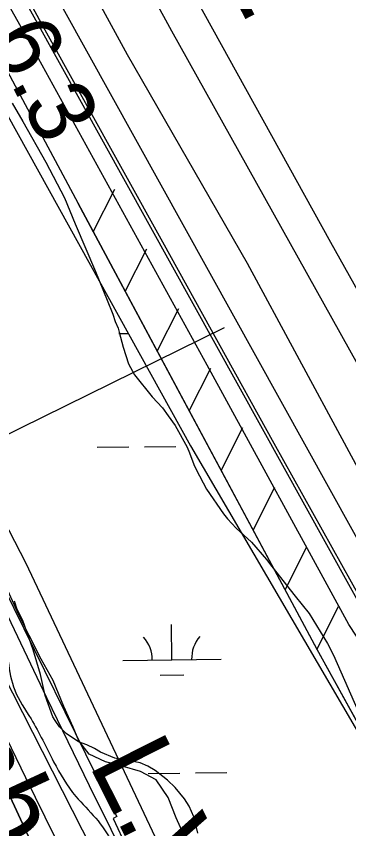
# Model space of a CAD drawing. Extents: x 3684037 to 3722149, y 433263 to 459021.
# Drawn here: x 3712028 to 3712366, y 440224 to 441051 of the extents above; entities that cross this region are included whole.
import ezdxf

# ---------------------------------------------------------------- set-up
doc = ezdxf.new("R2010")
doc.units = 0
for name, color, linetype in [('V-FLOD-BASE', 7, 'Continuous'), ('V-LEVE-TOET', 7, 'Continuous'), ('V-RIVR-EDGE', 7, 'Continuous'), ('V-RIVR-IDEN', 7, 'Continuous'), ('V-RIVR-RANG', 7, 'Continuous'), ('V-RIVR-RANG-IDEN', 7, 'Continuous'), ('V-ROAD-CNTR', 7, 'Continuous'), ('V-RRAP-FSHR', 7, 'Continuous'), ('V-RRAP-RVMT', 7, 'Continuous'), ('V-SITE-VEGE', 7, 'Continuous'), ('V-SURV-LINE', 7, 'Continuous'), ('V-TOPO-DPTH', 7, 'Continuous'), ('V-TOPO-MINR', 7, 'Continuous'), ('V-TOPO-WATR', 7, 'Continuous'), ('V-TOPO-WATR-IDEN', 7, 'Continuous'), ('V-UTIL-IDEN', 7, 'Continuous'), ('V-WETL-SWMP', 7, 'Continuous')]:
    doc.layers.add(name, color=color, linetype=linetype)

msp = doc.modelspace()

# ---------------------------------------------------------------- linework, layer by layer
at = {"layer": 'V-FLOD-BASE'}
msp.add_lwpolyline([(3712398.74, 440422.41), (3712290.71, 440616.44), (3712177.45, 440821.47), (3712056.06, 441040.41), (3711925.95, 441279.62), (3711796.44, 441506.66), (3711752.3, 441587.16), (3711730.23, 441628.29), (3711718.6, 441652.61), (3711654.1, 441794.53), (3711570.43, 441978.74), (3711454.8, 442224.92)], dxfattribs=at)
at = {"layer": 'V-LEVE-TOET'}
for points in [[(3711516.68, 442246.95), (3711627.09, 442006.55), (3711773.51, 441696.66), (3711965.19, 441335.23), (3712141.19, 441012.62), (3712263.15, 440800.06), (3712414.75, 440519.15), (3712489.08, 440395.79), (3712504.77, 440365.67), (3712551.23, 440281.69), (3712698.85, 440026.88)], [(3712594.9, 440025.08), (3712449.12, 440283.98), (3712438.67, 440303.09), (3712428.22, 440316.99), (3712416.03, 440329.72), (3712408.48, 440342.46), (3712402.09, 440356.95), (3712396.85, 440373.75), (3712391.04, 440388.23), (3712382.9, 440407.34), (3712366.65, 440432.25), (3712222.6, 440696.36), (3712039.64, 441028.82), (3711814.87, 441429.61), (3711723.69, 441588.89), (3711716.72, 441602.79), (3711694.64, 441649.13), (3711565.06, 441926.01), (3711441.87, 442202.32)]]:
    msp.add_lwpolyline(points, dxfattribs=at)
at = {"layer": 'V-RIVR-EDGE'}
msp.add_spline([(3710881.85, 442907.17), (3710900.3, 442872.76), (3710912.89, 442844.25), (3710926.84, 442815.27), (3710939.89, 442789.92), (3710950.22, 442762.31), (3710961.88, 442723.85), (3710972.69, 442706.64), (3710987.55, 442681.29), (3711004.19, 442645.52), (3711013.15, 442612.95), (3711017.62, 442590.33), (3711028.39, 442559.55), (3711043.23, 442525.61), (3711061.24, 442493.46), (3711083.32, 442464.01), (3711101.79, 442435.48), (3711123.37, 442385.69), (3711146.29, 442329.57), (3711160.2, 442285.22), (3711177.71, 442238.15), (3711205.6, 442178.4), (3711227.63, 442127.25), (3711258.71, 442079.24), (3711273.08, 442038.51), (3711277.08, 442009.57), (3711279.27, 441982.43), (3711285.11, 441965.69), (3711299.53, 441946.66), (3711314.4, 441925.82), (3711322.93, 441901.39), (3711344.09, 441864.26), (3711361.61, 441818.09), (3711381.38, 441766.05), (3711387.6, 441724.88), (3711408.3, 441685.04), (3711430.33, 441634.35), (3711446.97, 441597.23), (3711483.42, 441524.79), (3711505.9, 441474.1), (3711521.64, 441439.69), (3711545.49, 441393.97), (3711577.41, 441319.28), (3711605.29, 441255.01), (3711666.49, 441137.74), (3711693.94, 441084.32), (3711722.25, 441011.45), (3711736.18, 440977.51), (3711773.54, 440908.24), (3711800.07, 440850.29), (3711813.99, 440812.28), (3711827.94, 440785.11), (3711836.49, 440767.46), (3711872.07, 440711.3), (3711903.57, 440647.92), (3711936.4, 440576.4), (3711963.82, 440513.48), (3711991.74, 440467.29), (3712009.3, 440437.41), (3712020.05, 440394.43), (3712026.76, 440365.47), (3712043.42, 440336.04), (3712066.37, 440292.58), (3712088.89, 440257.25), (3712109.18, 440235.05), (3712138.9, 440183.88), (3712150.57, 440149.03), (3712155.9, 440111.04), (3712162.18, 440090.68), (3712177.89, 440044.52), (3712191.39, 440016), (3712212.53, 439972.54), (3712246.76, 439918.65), (3712265.21, 439881.98), (3712282.72, 439834), (3712320.51, 439756.14), (3712342.1, 439710.42), (3712373.62, 439655.63), (3712403.35, 439610.34), (3712425.83, 439558.28), (3712451.47, 439505.77), (3712470.39, 439476.33), (3712503.75, 439435.1), (3712518.6, 439408.84), (3712544.23, 439350.45), (3712559.09, 439322.83), (3712605.51, 439263.94), (3712623.98, 439233.6), (3712641.51, 439193.31), (3712662.18, 439142.17), (3712689.17, 439086.03), (3712722.5, 439033.5), (3712753.58, 438981.88), (3712765.15, 438962.6)], degree=3, dxfattribs=at)
at = {"layer": 'V-RIVR-RANG'}
msp.add_line((3712239.87, 440734.11), (3711486.16, 440363.28), dxfattribs=at)
at = {"layer": 'V-ROAD-CNTR'}
msp.add_lwpolyline([(3710393.02, 444727.69), (3710641.61, 444250), (3710817.86, 443893.88), (3711037.73, 443419.98), (3711197.76, 443070.03), (3711490.99, 442422.97), (3711750.12, 441857.32), (3711840.88, 441668.92), (3712186.17, 441036.48), (3712590.75, 440311.07), (3712879.98, 439780.16), (3713036.49, 439491.2), (3713175.22, 439193.41), (3713278.17, 438972.16)], dxfattribs=at)
at = {"layer": 'V-RRAP-FSHR'}
for p, q in [((3712106.7, 440831.92), (3712128.75, 440875.49)), ((3712106.7, 440831.92), (3712128.75, 440875.49)), ((3712139.2, 440771.2), (3712161.25, 440814.77)), ((3712139.2, 440771.2), (3712161.25, 440814.77)), ((3712171.7, 440710.47), (3712193.75, 440754.04)), ((3712171.7, 440710.47), (3712193.75, 440754.04)), ((3712204.19, 440649.75), (3712226.25, 440693.32)), ((3712204.19, 440649.75), (3712226.25, 440693.32)), ((3712236.69, 440589.03), (3712258.74, 440632.6)), ((3712236.69, 440589.03), (3712258.74, 440632.6)), ((3712269.19, 440528.3), (3712291.24, 440571.87)), ((3712269.19, 440528.3), (3712291.24, 440571.87)), ((3712301.69, 440467.58), (3712323.74, 440511.15)), ((3712301.69, 440467.58), (3712323.74, 440511.15)), ((3712334.19, 440406.86), (3712356.24, 440450.43)), ((3712334.19, 440406.86), (3712356.24, 440450.43))]:
    msp.add_line(p, q, dxfattribs=at)
for points in [[(3710219.36, 444700.16), (3710405.05, 444328.82), (3710632.08, 443905.61), (3710829.82, 443472.46), (3710874.19, 443372.05), (3710940.18, 443211.19), (3711150.7, 442775.78), (3711369.41, 442270.41), (3711583.94, 441827.2), (3711640.29, 441693.5), (3711911.6, 441196.46), (3712334.08, 440407.06), (3712777.04, 439605.31), (3712909.03, 439353.17), (3713100.31, 438966.64)], [(3710449.88, 443948.54), (3711032.4, 442732.84), (3711461.51, 441700.35), (3711800.31, 440955.81), (3712037.99, 440494.59), (3712458, 439603.75), (3712696.92, 439205.07), (3712836.7, 438963.43)], [(3712091.06, 440861.14), (3712334.08, 440407.06), (3712426.09, 440240.53)]]:
    msp.add_lwpolyline(points, dxfattribs=at)
at = {"layer": 'V-RRAP-RVMT'}
for p, q in [((3712015.42, 440470.27), (3712119.61, 440258.65)), ((3712119.61, 440258.65), (3712118.9, 440258.34)), ((3712118.9, 440258.34), (3712130.54, 440236.87)), ((3712130.54, 440236.87), (3712126.88, 440234.82)), ((3712126.88, 440234.82), (3712178.95, 440122.56))]:
    msp.add_line(p, q, dxfattribs=at)
at = {"layer": 'V-SITE-VEGE'}
for p, q in [((3712024.19, 440963.01), (3712035.12, 440944.38)), ((3712035.12, 440944.38), (3712058.4, 440902.9)), ((3712058.4, 440902.9), (3712077.42, 440866.54)), ((3712077.42, 440866.54), (3712088.41, 440839.95)), ((3712088.41, 440839.95), (3712108.94, 440791.43)), ((3712108.94, 440791.43), (3712120.89, 440762.5)), ((3712120.89, 440762.5), (3712126.62, 440748.04)), ((3712126.62, 440748.04), (3712129.02, 440740.56)), ((3712129.02, 440740.56), (3712131.89, 440734.03)), ((3712131.89, 440734.03), (3712132.86, 440729.83)), ((3712132.86, 440729.83), (3712137.2, 440714.42)), ((3712137.2, 440714.42), (3712142.49, 440697.61)), ((3712142.49, 440697.61), (3712148.67, 440686.42)), ((3712148.67, 440686.42), (3712166.64, 440664.1)), ((3712166.64, 440664.1), (3712177.03, 440652.95)), ((3712177.03, 440652.95), (3712182.72, 440644.57)), ((3712182.72, 440644.57), (3712189.82, 440634.79)), ((3712189.82, 440634.79), (3712202.17, 440612.89)), ((3712202.17, 440612.89), (3712204.57, 440606.83)), ((3712204.57, 440606.83), (3712208.88, 440595.16)), ((3712208.88, 440595.16), (3712211.26, 440590.03)), ((3712211.26, 440590.03), (3712221.72, 440569.98)), ((3712221.72, 440569.98), (3712239.25, 440544.85)), ((3712239.25, 440544.85), (3712243.04, 440539.73)), ((3712243.04, 440539.73), (3712252.01, 440530.44)), ((3712252.01, 440530.44), (3712267.58, 440516.05)), ((3712267.58, 440516.05), (3712282.71, 440498.39)), ((3712282.71, 440498.39), (3712288.38, 440491.41)), ((3712288.38, 440491.41), (3712312.04, 440461.18)), ((3712312.04, 440461.18), (3712326.23, 440443.51)), ((3712029.38, 440447.61), (3712026.5, 440456.02)), ((3712035.1, 440436.42), (3712029.38, 440447.61)), ((3712326.23, 440443.51), (3712344.74, 440412.76)), ((3712045.64, 440406.55), (3712035.1, 440436.42)), ((3712344.74, 440412.76), (3712350.92, 440401.11)), ((3712052.87, 440381.33), (3712045.64, 440406.55)), ((3712350.92, 440401.11), (3712379.55, 440336.27)), ((3712057.73, 440359.83), (3712052.87, 440381.33)), ((3712065.4, 440338.36), (3712057.73, 440359.83)), ((3712067.77, 440334.63), (3712065.4, 440338.36)), ((3712072.5, 440328.12), (3712067.77, 440334.63)), ((3712079.11, 440321.15), (3712072.5, 440328.12)), ((3712091.82, 440312.83), (3712079.11, 440321.15)), ((3712100.28, 440309.62), (3712091.82, 440312.83)), ((3712107.8, 440305.94), (3712100.28, 440309.62)), ((3712113.91, 440302.24), (3712107.8, 440305.94)), ((3712128.48, 440296.28), (3712113.91, 440302.24)), ((3712135.04, 440294.92), (3712128.48, 440296.28)), ((3712137.85, 440294.48), (3712135.04, 440294.92)), ((3712154.27, 440291.34), (3712137.85, 440294.48)), ((3712162.25, 440288.13), (3712154.27, 440291.34)), ((3712169.78, 440283.51), (3712162.25, 440288.13)), ((3712182.03, 440273.78), (3712169.78, 440283.51)), ((3712190.05, 440266.35), (3712182.03, 440273.78)), ((3712199.51, 440254.73), (3712190.05, 440266.35)), ((3712204.25, 440247.28), (3712199.51, 440254.73)), ((3712209.02, 440236.55), (3712204.25, 440247.28)), ((3712212.91, 440219.73), (3712209.02, 440236.55))]:
    msp.add_line(p, q, dxfattribs=at)
at = {"layer": 'V-SURV-LINE'}
for points in [[(3711755.82, 441636.9), (3712986.54, 439416.05)], [(3712960.3, 439401.52), (3711729.57, 441622.37)]]:
    msp.add_lwpolyline(points, dxfattribs=at)
at = {"layer": 'V-TOPO-DPTH'}
for points in [[(3712159.9, 439958.74), (3711790.59, 440757.32), (3711778.05, 440784.26), (3711765.44, 440811.17), (3711752.69, 440838.01), (3711739.87, 440864.82), (3711470.78, 441423.94), (3711461.78, 441442.85), (3711452.91, 441461.81), (3711444.21, 441480.85), (3711435.62, 441499.95), (3711427.28, 441519.14), (3711419.15, 441538.43), (3711411.32, 441557.84), (3711403.71, 441577.34), (3711290.02, 441875.64), (3711251.68, 441974.24), (3711212.45, 442072.47), (3711171.9, 442170.16)], [(3711171.9, 442170.16), (3711212.45, 442072.47), (3711251.68, 441974.24), (3711290.02, 441875.64), (3711403.71, 441577.34), (3711411.32, 441557.84), (3711419.15, 441538.43), (3711427.28, 441519.14), (3711435.62, 441499.95), (3711444.21, 441480.85), (3711452.91, 441461.81), (3711461.78, 441442.85), (3711470.78, 441423.94), (3711739.87, 440864.82), (3711752.69, 440838.01), (3711765.44, 440811.17), (3711778.05, 440784.26), (3711790.59, 440757.32), (3712159.9, 439958.74)], [(3712197.32, 440022.68), (3711902.32, 440602.62), (3711883.7, 440639.56), (3711865.26, 440676.58), (3711847.08, 440713.74), (3711829.08, 440750.98), (3711797.4, 440817.16), (3711795.38, 440821.39), (3711793.38, 440825.62), (3711791.39, 440829.86), (3711789.41, 440834.1), (3711765.23, 440886.19), (3711751.28, 440916.54), (3711737.49, 440946.95), (3711723.93, 440977.47), (3711710.52, 441008.06), (3711483.56, 441531.41)]]:
    msp.add_lwpolyline(points, dxfattribs=at)
at = {"layer": 'V-TOPO-MINR'}
for points in [[(3712159.9, 439958.74), (3711790.59, 440757.32), (3711778.05, 440784.26), (3711765.44, 440811.17), (3711752.69, 440838.01), (3711739.87, 440864.82), (3711470.78, 441423.94), (3711461.78, 441442.85), (3711452.91, 441461.81), (3711444.21, 441480.85), (3711435.62, 441499.95), (3711427.28, 441519.14), (3711419.15, 441538.43), (3711411.32, 441557.84), (3711403.71, 441577.34), (3711290.02, 441875.64), (3711251.68, 441974.24), (3711212.45, 442072.47), (3711171.9, 442170.16)], [(3712146.88, 440178.99), (3712102.85, 440268.13), (3712059.39, 440357.55), (3712016.81, 440447.38), (3711974.8, 440537.49), (3711847.44, 440814.18), (3711840.05, 440830.07), (3711832.6, 440845.92), (3711825.02, 440861.71), (3711817.37, 440877.47), (3711701.86, 441113.24)], [(3712087.75, 440175.37), (3712038.19, 440276.14), (3711989.02, 440377.09), (3711940.41, 440478.31), (3711892.19, 440579.72), (3711790.16, 440795.86), (3711784.83, 440807.15), (3711779.5, 440818.44), (3711774.18, 440829.73), (3711768.86, 440841.02), (3711696.6, 440994.29), (3711655.51, 441082.38)]]:
    msp.add_lwpolyline(points, dxfattribs=at)
at = {"layer": 'V-TOPO-WATR'}
msp.add_lwpolyline([(3712197.32, 440022.68), (3711902.32, 440602.62), (3711883.7, 440639.56), (3711865.26, 440676.58), (3711847.08, 440713.74), (3711829.08, 440750.98), (3711797.4, 440817.16), (3711795.38, 440821.39), (3711793.38, 440825.62), (3711791.39, 440829.86), (3711789.41, 440834.1), (3711765.23, 440886.19), (3711751.28, 440916.54), (3711737.49, 440946.95), (3711723.93, 440977.47), (3711710.52, 441008.06), (3711483.56, 441531.41)], dxfattribs=at)
at = {"layer": 'V-UTIL-IDEN'}
for points in [[(3710219.36, 444700.16), (3710405.05, 444328.82), (3710632.08, 443905.61), (3710829.82, 443472.46), (3710874.19, 443372.05), (3710940.18, 443211.19), (3711150.7, 442775.78), (3711369.41, 442270.41), (3711583.94, 441827.2), (3711640.29, 441693.5), (3711911.6, 441196.46), (3712334.08, 440407.06), (3712777.04, 439605.31), (3712909.03, 439353.17), (3713100.31, 438966.64)], [(3712091.06, 440861.14), (3712334.08, 440407.06), (3712426.09, 440240.53)]]:
    msp.add_lwpolyline(points, dxfattribs=at)
at = {"layer": 'V-WETL-SWMP'}
for p, q in [((3711654.21, 441609.79), (3712205.56, 440614.23)), ((3712145.73, 441187.46), (3712347.94, 440821.59)), ((3712347.94, 440821.59), (3712529.3, 440495.9)), ((3712132.83, 440728.32), (3712142.31, 440728.43)), ((3712205.56, 440614.23), (3712487.72, 440130.65)), ((3712110.77, 440612.63), (3712142.76, 440613)), ((3712158.76, 440613.18), (3712190.76, 440613.56)), ((3712030.91, 440441.96), (3712019.87, 440466.87)), ((3712041.37, 440421.11), (3712030.91, 440441.96)), ((3712186.7, 440396.25), (3712186.28, 440432.25)), ((3712053.57, 440396.78), (3712041.37, 440421.11)), ((3712065.77, 440375.35), (3712053.57, 440396.78)), ((3712136.7, 440395.67), (3712236.69, 440396.83)), ((3712076.81, 440348.7), (3712065.77, 440375.35)), ((3712174.88, 440380.68), (3712198.88, 440380.96)), ((3712086.11, 440327.85), (3712076.81, 440348.7)), ((3712091.92, 440313.95), (3712086.11, 440327.85)), ((3712102.37, 440300.05), (3712091.92, 440313.95)), ((3712119.19, 440292.54), (3712102.37, 440300.05)), ((3712136, 440287.92), (3712119.19, 440292.54)), ((3712154.55, 440282.72), (3712136, 440287.92)), ((3712170.79, 440274.05), (3712154.55, 440282.72)), ((3712162.63, 440280.53), (3712194.63, 440280.9)), ((3712210.63, 440281.09), (3712242.63, 440281.46)), ((3712182.98, 440256.1), (3712170.79, 440274.05)), ((3712191.12, 440235.24), (3712182.98, 440256.1)), ((3712201, 440212.65), (3712191.12, 440235.24))]:
    msp.add_line(p, q, dxfattribs=at)
for centre, start, end in [((3712131.45, 440396.08), 359.89487, 41.43852), ((3712241.93, 440397.37), 139.89487, 181.43852)]:
    msp.add_arc(centre, 35.25, start, end, dxfattribs=at)

# ---------------------------------------------------------------- texts
at = {"layer": 'V-RIVR-IDEN'}
msp.add_text('September', height=83, rotation=294.90477, dxfattribs=at).set_placement((3711814.61, 440599.85))
at = {"layer": 'V-RIVR-RANG'}
msp.add_text('6.3', height=67, rotation=297.21833, dxfattribs=at).set_placement((3711999.24, 441028.45))
at = {"layer": 'V-RIVR-RANG-IDEN'}
msp.add_text('R-63.9', height=83, rotation=27.35748, dxfattribs=at).set_placement((3712253.33, 441044.35))
at = {"layer": 'V-TOPO-WATR-IDEN'}
msp.add_text('L.W.R.P.', height=83, rotation=296.79822, dxfattribs=at).set_placement((3712101.55, 440290.4))

doc.saveas('drawing.dxf')
